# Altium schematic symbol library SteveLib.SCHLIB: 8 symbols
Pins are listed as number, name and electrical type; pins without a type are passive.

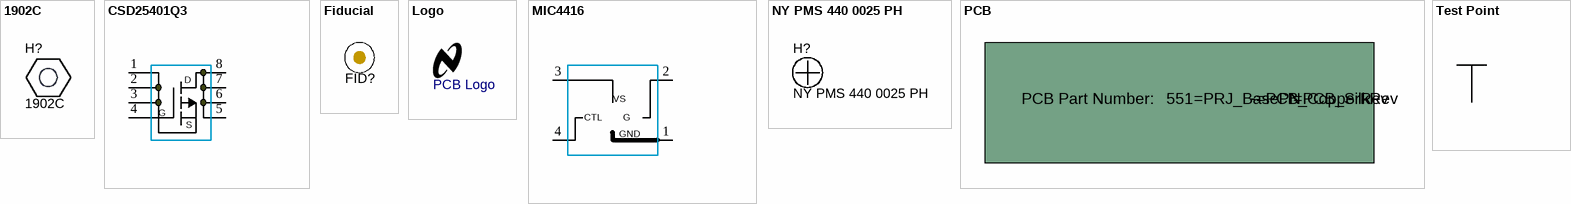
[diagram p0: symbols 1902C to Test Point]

## 1902C
designator H?
Standoff, Hex, 0.5"L #4-40 Nylon; Manufacturer: Keystone; CompType: Hardware; U/M: EA
footprint Keystone_1902C (Hex Standoff, 4-40 threaded, nylon)

## CSD25401Q3
designator U?
Manufacturer: Texas Instruments; SymbolVersion: use current date i.e. 2008-05-20; SymbolCreator: Use LDAP id; CompType: Used in some BOM reports.  Useful for finding later.; U/M: EA, IN, or GM
pins: 1 S, 2 S, 3 S, 4 G, 5 D, 6 D, 7 D, 8 D

## Fiducial
designator FID?  (value not drawn)
Fiducial mark.  There is nothing to buy or mount.; SymbolCreator: codlsc
footprint Fiducial10-30
footprint Fiducial10-20
footprint Fiducial15-30
footprint Fiducial20-40
footprint Fiducial6.4-20

## Logo
designator Logo?, comment PCB Logo  (no BOM)
National Semiconductor logo or worldmark; SymbolCreator: codlsc
footprint Logo_CopperSolderMask_Large
footprint Logo_CopperSolderMask_Medium
footprint Logo_Overlay_Large
footprint Logo_Overlay_Medium
footprint Logo_Copper_Large
footprint Logo_Copper_Medium
footprint Logo_SolderMask_Large
footprint Logo_SolderMask_Medium
footprint Worldmark_CopperSolderMask_Small
footprint Worldmark_Overlay_Medium
footprint Worldmark_Overlay_Small
footprint Worldmark_Copper_Medium
footprint Worldmark_Copper_Small
footprint Worldmark_SolderMask_Medium
footprint Worldmark_SolderMask_Small
footprint Worldmark_CopperSolderMask_Medium

## MIC4416
designator U?
Manufacturer: Micrel; SymbolVersion: use current date i.e. 2008-05-20; SymbolCreator: Use LDAP id; CompType: Used in some BOM reports.  Useful for finding later.; U/M: EA, IN, or GM
pins: 1 GND, 2 G, 3 VS, 4 CTL

## NY PMS 440 0025 PH
designator H?
Machine Screw, Round, #4-40 x 1/4, Nylon, Philips panhead; Manufacturer: B&F Fastener Supply; CompType: Hardware; SymbolCreator: codlsc; U/M: EA
footprint NY PMS 440 0025 PH (4-40 screw and mounting hold)

## PCB
designator AA?, comment Printed Circuit Board  (value not drawn)  (mechanical)
Manufacturer: TBD; PartNumber: Used in BOM Report; CompType: PCB; SymbolCreator: codlsc; U/M: EA

## Test Point
designator TP?, comment SMD Testpoint
Manufacturer: Used in BOM report; SymbolVersion: use current date i.e. 2008-05-20; SymbolCreator: Use LDAP id; CompType: Used in some BOM reports.  Useful for finding later.; U/M: EA, IN, or GM
footprint TestPoint SMD
pins: 1 TP "SMD Testpoint"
